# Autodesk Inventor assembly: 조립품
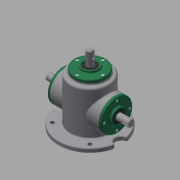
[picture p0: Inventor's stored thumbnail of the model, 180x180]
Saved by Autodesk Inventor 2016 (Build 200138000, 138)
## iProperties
Created: 2018-04
Part Number: 조립품
Material: 일반
Document SubType Name: Weldment
Designer: 605-17
Weld Material: Welded Aluminum-6061
Author: 605-17
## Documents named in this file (16)
- C:\Users\605-17\Desktop\480407V1005\조립품.iam
- C:\Users\605-17\Desktop\480407V1005\본체.ipt
- C:\Users\605-17\Desktop\480407V1005\커버.ipt
- C:\Users\605-17\Desktop\480407V1005\베어링 6203.ipt
- C:\Users\605-17\Desktop\480407V1005\오일 실.ipt
- 오일 실.ipt
- C:\Users\605-17\Desktop\480407V1005\메인 축.ipt
- 메인 축.ipt
- C:\Users\605-17\Desktop\480407V1005\키 5x5.ipt
- C:\Users\605-17\Desktop\480407V1005\메인 베벨기어.ipt
- C:\Users\605-17\Desktop\480407V1005\서브 축.ipt
- 서브 축.ipt
- C:\Users\605-17\Desktop\480407V1005\키 4x4.ipt
- C:\Users\605-17\Desktop\480407V1005\서브 베벨기어.ipt
- C:\Users\605-17\Desktop\480407V1005\볼트 M4.ipt
- 볼트 M4.ipt
